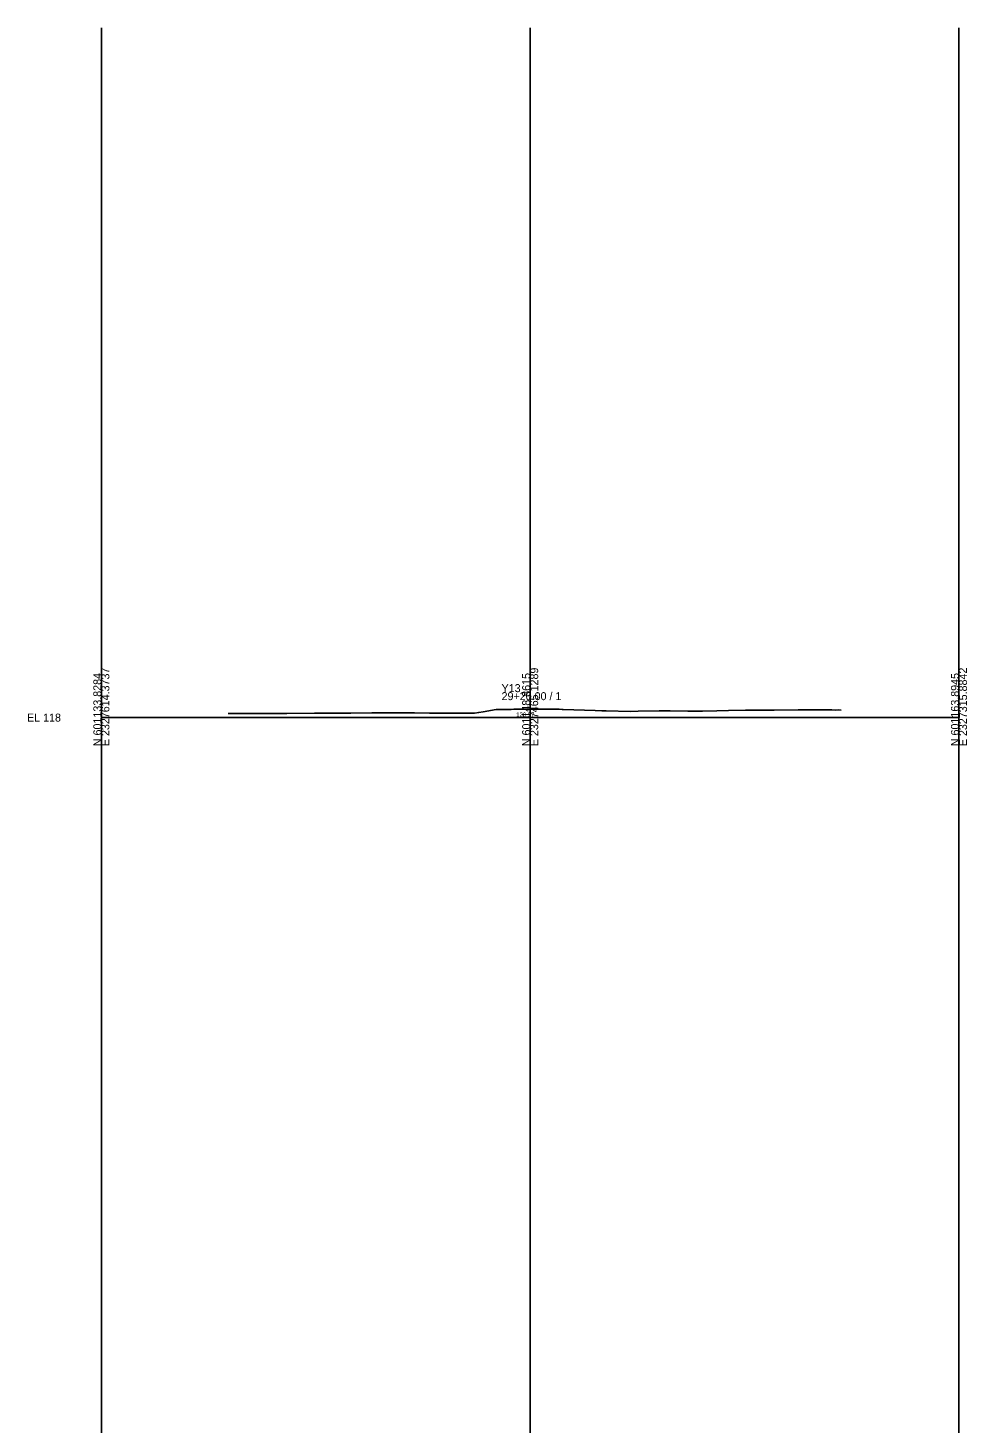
# Model space of a CAD drawing. Extents: x -26 to 1603, y -711 to 1241.
# Drawn here: x 1274.3 to 1602.8, y 753.1 to 1241.3 of the extents above; entities that cross this region are included whole.
import ezdxf

# ---------------------------------------------------------------- set-up
doc = ezdxf.new("R2010")
doc.units = 0
for name, color, linetype in [('Exist CMT Pavement', 7, 'Continuous'), ('Exist Cross Section Cell', 7, 'Continuous'), ('Exist XS Center Line Elevation Label', 7, 'Continuous'), ('Exist XS Ground Line', 7, 'Continuous'), ('Prop XS Earthwork Shape', 7, 'Continuous'), ('Scratch_Level_9', 7, 'Continuous')]:
    doc.layers.add(name, color=color, linetype=linetype)

msp = doc.modelspace()

# ---------------------------------------------------------------- linework, layer by layer
at = {"layer": 'Exist CMT Pavement'}
for p, q in [((1449.9, 1003.07), (1449.9, 1002.87)), ((1449.9, 1003.07), (1450, 1003.07)), ((1449.9, 1002.87), (1450, 1002.87)), ((1450.1, 1003.07), (1450, 1003.07)), ((1450.1, 1002.87), (1450, 1002.87)), ((1450.1, 1003.07), (1450.1, 1002.87))]:
    msp.add_line(p, q, dxfattribs=at)
at = {"layer": 'Exist Cross Section Cell'}
for p, q in [((1450, 1000), (1450, 1008.9)), ((1300, 1000), (1450, 1000)), ((1450, 1000), (1600, 1000))]:
    msp.add_line(p, q, dxfattribs=at)
at = {"layer": 'Exist XS Ground Line'}
msp.add_lwpolyline([(1344.38, 1001.47), (1353.68, 1001.48), (1354.43, 1001.48), (1361.19, 1001.46), (1364.48, 1001.45), (1364.85, 1001.45), (1374.54, 1001.54), (1376.03, 1001.55), (1384.59, 1001.54), (1387.21, 1001.55), (1394.64, 1001.64), (1398.39, 1001.61), (1404.69, 1001.63), (1409.56, 1001.62), (1414.74, 1001.56), (1424.13, 1001.54), (1427.82, 1001.52), (1430.48, 1001.55), (1432.01, 1001.82), (1433.6, 1002.07), (1438.16, 1002.78), (1438.63, 1002.78), (1439.06, 1002.8), (1439.75, 1002.81), (1441.33, 1002.84), (1443.37, 1002.89), (1444.33, 1002.91), (1444.95, 1002.91), (1446.79, 1002.93), (1448.13, 1002.95), (1449.4, 1002.96), (1449.77, 1002.97), (1451.43, 1002.95), (1452.24, 1002.95), (1453.05, 1002.95), (1454.97, 1002.94), (1457.7, 1002.92), (1458.06, 1002.92), (1460.19, 1002.9), (1461.23, 1002.89), (1461.58, 1002.88), (1472.77, 1002.5), (1475.05, 1002.4), (1476.63, 1002.4), (1485.11, 1002.19), (1487.81, 1002.22), (1495.16, 1002.39), (1498.99, 1002.37), (1505.21, 1002.3), (1510.3, 1002.3), (1515.26, 1002.38), (1519.43, 1002.5), (1525.31, 1002.57), (1532.52, 1002.6), (1535.37, 1002.62), (1543.7, 1002.7), (1545.42, 1002.71), (1554.88, 1002.71), (1555.56, 1002.7), (1556.96, 1002.56), (1558.02, 1002.69), (1558.84, 1002.63)], dxfattribs=at)
at = {"layer": 'Prop XS Earthwork Shape'}
msp.add_lwpolyline([(1450.1, 1002.96), (1450.1, 1002.87), (1450, 1002.87), (1449.9, 1002.87), (1449.9, 1002.97)], close=True, dxfattribs=at)
at = {"layer": 'Scratch_Level_9'}
for p, q in [((1300, 1241.32), (1300, -141.18)), ((1450, 1241.32), (1450, -141.18)), ((1600, 1241.32), (1600, -141.18))]:
    msp.add_line(p, q, dxfattribs=at)

# ---------------------------------------------------------------- texts
at = {"layer": 'Exist Cross Section Cell'}
for s, p in [('N 601133.8284', (1300, 990)), ('E 2327614.3737', (1302.8, 990)), ('N 601148.8615', (1450, 990)), ('E 2327465.1289', (1452.8, 990)), ('N 601163.8945', (1600, 990)), ('E 2327315.8842', (1602.8, 990))]:
    msp.add_text(s, height=2.8, rotation=90, dxfattribs=at).set_placement(p)
for s, p in [('Y13', (1440, 1008.9)), ('29+20.00 / 1', (1440, 1006.1)), ('EL 118', (1274, 998.6))]:
    msp.add_text(s, height=2.8, dxfattribs=at).set_placement(p)
at = {"layer": 'Exist XS Center Line Elevation Label'}
msp.add_text('120.97', height=1.5, dxfattribs=at).set_placement((1445.13, 1000.3))

doc.saveas('drawing.dxf')
